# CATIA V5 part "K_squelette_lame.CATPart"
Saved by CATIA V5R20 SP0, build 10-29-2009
Part number: squelette_lame
Publications: "Point.10", "point_centre_liaison_glissière", "Plan.1", "Plan.2", "Point.8", "Droite.5", "Plan.3"
Bounding box of the stored display mesh (mm): x 100 to 100, y 0 to 0, z 20 to 40
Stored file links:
  G:\Khaled_CFAO_2011\SIL\SIL_GR2\pfradet\pfradet\Khaled\CAD_ThinkMOTION\K_squelette_lame.CATPart
  G:\Khaled_CFAO_2011\SIL\SIL_GR2\pfradet\pfradet\Khaled\CAD_ThinkMOTION\K_squelette.CATProduct
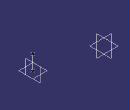
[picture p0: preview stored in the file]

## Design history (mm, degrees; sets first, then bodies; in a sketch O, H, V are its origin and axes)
Set1
  Point1 "point_centre_liaison_glissière": linked copy from another document
  Point2: linked copy from another document
  Plane1: linked copy from another document
  Plane2: linked copy from another document
Set2
  Point3: (0, 0, 0), relative to Point1
  Line1: type PtPt, FirstPoint Point1, SecondPoint Point2
  Plane3: type OffsetPt, RefPlane Plane1, RefPoint Point2
  Plane4: type OffsetPt, RefPlane Plane2, RefPoint Point2
Body1 (main body)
